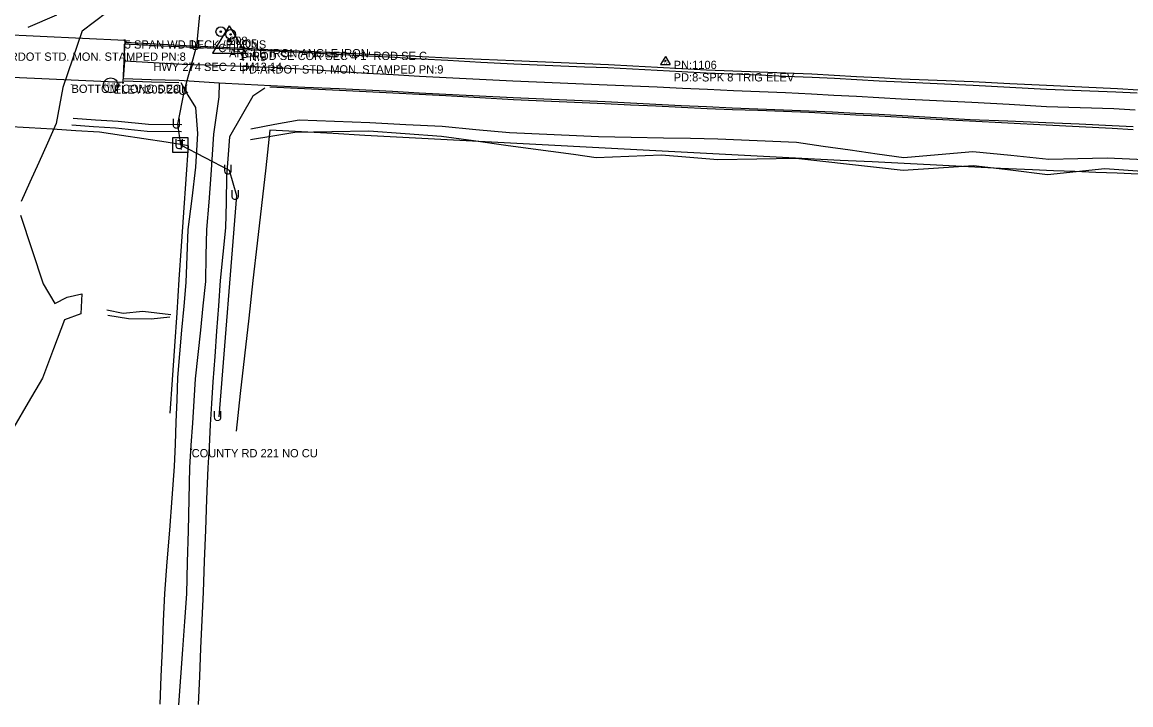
# Model space of a CAD drawing. Extents: x 1138803 to 1169983, y 1655906 to 1658226.
# Drawn here: x 1149238 to 1149908, y 1657086 to 1657498 of the extents above; entities that cross this region are included whole.
import ezdxf

# ---------------------------------------------------------------- set-up
doc = ezdxf.new("R2010")
doc.units = 0
for name, color, linetype in [('Default', 7, 'Continuous'), ('S_BRIDGE', 7, 'Continuous'), ('S_BRIDGE_ANNOT', 7, 'Continuous'), ('S_DITCHLINE', 7, 'Continuous'), ('S_EDGE_PAVEMENT', 7, 'Continuous'), ('S_GRAVEL_ROAD', 7, 'Continuous'), ('S_HIST_HIGH_WATER', 7, 'Continuous'), ('S_HIST_HIGH_WATER_ANNOT', 7, 'Continuous'), ('S_IRON_PIN', 7, 'Continuous'), ('S_IRON_PIN_ANNOT', 7, 'Continuous'), ('S_MSC_PT_SYM', 7, 'Continuous'), ('S_PAVEMENT_CROWN', 7, 'Continuous'), ('S_PRIMARY_CTL', 7, 'Continuous'), ('S_PRIMARY_CTL_ANNOT', 7, 'Continuous'), ('S_SECONDARY_CTL', 7, 'Continuous'), ('S_SECONDARY_CTL_ANNOT', 7, 'Continuous'), ('S_SHOULDER', 7, 'Continuous'), ('S_STR_PT_SYM', 7, 'Continuous'), ('S_STREAM', 7, 'Continuous'), ('S_SURVEY_TEXT_ANNOT', 7, 'Continuous'), ('S_TELEPHONE_UTILITIES', 7, 'Continuous'), ('S_TREE', 7, 'Continuous'), ('S_UNDERGROUND_CABLE', 7, 'Continuous'), ('S_UTL_PT_SYM', 7, 'Continuous')]:
    doc.layers.add(name, color=color, linetype=linetype)

msp = doc.modelspace()

# ---------------------------------------------------------------- linework, layer by layer
at = {"layer": 'S_BRIDGE'}
for p, q in [((1149223.22, 1657490.51), (1149300.02, 1657486.84)), ((1149300.02, 1657486.84), (1149298.91, 1657461.36)), ((1149298.91, 1657461.36), (1149221.93, 1657464.92))]:
    msp.add_line(p, q, dxfattribs=at)
at = {"layer": 'S_DITCHLINE'}
for points in [[(1149334.47, 1657435.85), (1149314.27, 1657436.03), (1149295.98, 1657437.74), (1149282.4, 1657438.69), (1149268.82, 1657439.65)], [(1149920.24, 1657414.54), (1149906.71, 1657415.09), (1149893.18, 1657415.65), (1149875.65, 1657415.27), (1149858.11, 1657414.9), (1149835.11, 1657417.24), (1149812.12, 1657419.57), (1149791.31, 1657417.7), (1149770.51, 1657415.83), (1149754.3, 1657418.14), (1149738.08, 1657420.44), (1149721.87, 1657422.74), (1149705.66, 1657425.05), (1149681.88, 1657426.12), (1149658.1, 1657427.19), (1149641.75, 1657427.48), (1149625.41, 1657427.78), (1149605.8, 1657428.18), (1149586.2, 1657428.59), (1149572.75, 1657429.17), (1149559.3, 1657429.76), (1149545.84, 1657430.34), (1149532.39, 1657430.92), (1149512.02, 1657432.82), (1149491.64, 1657434.71), (1149469.8, 1657435.85), (1149447.95, 1657437), (1149426.61, 1657437.82), (1149405.27, 1657438.65), (1149390.73, 1657435.92), (1149376.2, 1657433.2)], [(1149334.24, 1657431.56), (1149313.65, 1657431.84), (1149294.45, 1657433.82), (1149281.22, 1657434.67), (1149268, 1657435.52)], [(1149920.09, 1657407.18), (1149906, 1657408.18), (1149891.91, 1657409.19), (1149874.6, 1657407.43), (1149857.28, 1657405.67), (1149834.91, 1657408.41), (1149812.54, 1657411.15), (1149791.33, 1657409.71), (1149770.12, 1657408.28), (1149753.93, 1657410.09), (1149737.74, 1657411.91), (1149721.54, 1657413.72), (1149705.35, 1657415.54), (1149681.79, 1657415.15), (1149658.23, 1657414.75), (1149641.18, 1657416.15), (1149624.13, 1657417.54), (1149604.37, 1657416.75), (1149584.61, 1657415.96), (1149570.98, 1657417.8), (1149557.35, 1657419.64), (1149543.72, 1657421.48), (1149530.09, 1657423.32), (1149510.67, 1657426.05), (1149491.26, 1657428.79), (1149469.29, 1657430.41), (1149447.33, 1657432.03), (1149425.03, 1657431.56), (1149402.74, 1657431.1), (1149389.4, 1657428.88), (1149376.06, 1657426.67)], [(1149289.29, 1657324.09), (1149299.05, 1657322.02), (1149311, 1657323.36), (1149327.89, 1657321.3)], [(1149327.24, 1657319.71), (1149315.89, 1657318.44), (1149302.28, 1657318.68), (1149289.75, 1657320.58)]]:
    msp.add_lwpolyline(points, dxfattribs=at)
at = {"layer": 'S_EDGE_PAVEMENT'}
for points in [[(1149909.02, 1657434.65), (1149896.39, 1657435.26), (1149876.32, 1657436.16), (1149856.26, 1657437.06), (1149833.38, 1657437.96), (1149810.5, 1657438.86), (1149790, 1657440.06), (1149769.5, 1657441.26), (1149755.45, 1657441.96), (1149741.4, 1657442.66), (1149727.34, 1657443.36), (1149713.29, 1657444.06), (1149697.81, 1657444.69), (1149682.33, 1657445.32), (1149666.84, 1657445.95), (1149651.36, 1657446.58), (1149636.03, 1657447.36), (1149620.71, 1657448.13), (1149605.38, 1657448.9), (1149590.06, 1657449.68), (1149576.21, 1657450.3), (1149562.35, 1657450.92), (1149548.5, 1657451.54), (1149534.65, 1657452.17), (1149514.25, 1657453.18), (1149493.85, 1657454.2), (1149477.76, 1657455.02), (1149461.68, 1657455.84), (1149445.59, 1657456.66), (1149429.51, 1657457.48), (1149408.83, 1657458.42), (1149388.15, 1657459.35), (1149372.61, 1657460.19), (1149357.07, 1657461.03), (1149332.96, 1657462.66), (1149316.07, 1657463.07), (1149299.18, 1657463.49), (1149300.05, 1657474.26), (1149299.88, 1657484.48)], [(1149911.44, 1657454.9), (1149898.49, 1657455.58), (1149877.6, 1657456.34), (1149856.72, 1657457.11), (1149834.5, 1657458.33), (1149812.29, 1657459.56), (1149790.71, 1657460.55), (1149769.13, 1657461.55), (1149755.61, 1657462.27), (1149742.1, 1657462.98), (1149728.58, 1657463.69), (1149715.06, 1657464.4), (1149699.1, 1657465.06), (1149683.13, 1657465.72), (1149667.16, 1657466.38), (1149651.19, 1657467.03), (1149636.34, 1657467.81), (1149621.49, 1657468.59), (1149606.64, 1657469.36), (1149591.79, 1657470.14), (1149577.57, 1657470.71), (1149563.36, 1657471.28), (1149549.14, 1657471.86), (1149534.92, 1657472.43), (1149515.05, 1657473.51), (1149495.18, 1657474.59), (1149479.18, 1657475.49), (1149463.18, 1657476.38), (1149447.18, 1657477.28), (1149431.18, 1657478.17), (1149410.39, 1657479.22), (1149389.59, 1657480.27), (1149376.52, 1657480.89), (1149363.44, 1657481.5), (1149350.37, 1657482.12), (1149337.29, 1657482.74), (1149318.58, 1657483.61), (1149299.88, 1657484.48)]]:
    msp.add_lwpolyline(points, dxfattribs=at)
at = {"layer": 'S_GRAVEL_ROAD'}
for points in [[(1149333.8, 1657461.4), (1149338.18, 1657453.72), (1149342.77, 1657446.24), (1149344.05, 1657430.53), (1149342.78, 1657410.16), (1149340.46, 1657391.36), (1149338.13, 1657372.56), (1149337.49, 1657356.59), (1149336.84, 1657340.62), (1149335.61, 1657326.26), (1149334.37, 1657311.89), (1149333.14, 1657297.53), (1149331.91, 1657283.17), (1149331.41, 1657269.75), (1149330.91, 1657256.32), (1149330.41, 1657242.9), (1149329.91, 1657229.48), (1149328.44, 1657210.29), (1149326.96, 1657191.1), (1149325.49, 1657171.9), (1149324.02, 1657152.71), (1149323.3, 1657136.05), (1149322.57, 1657119.38), (1149321.85, 1657102.71), (1149321.12, 1657086.05)], [(1149384.53, 1657458.05), (1149377.43, 1657453.11), (1149370.36, 1657440.87), (1149363.28, 1657428.63), (1149361.44, 1657404.59), (1149361.19, 1657389.08), (1149360.93, 1657373.57), (1149359.34, 1657357.69), (1149357.74, 1657341.81), (1149356.62, 1657326.5), (1149355.5, 1657311.19), (1149354.37, 1657295.88), (1149353.25, 1657280.58), (1149352.47, 1657267.58), (1149351.69, 1657254.59), (1149350.91, 1657241.59), (1149350.13, 1657228.6), (1149349.43, 1657209.85), (1149348.73, 1657191.11), (1149348.03, 1657172.36), (1149347.33, 1657153.62), (1149346.58, 1657136.67), (1149345.82, 1657119.72), (1149345.07, 1657102.77), (1149344.31, 1657085.81)]]:
    msp.add_lwpolyline(points, dxfattribs=at)
at = {"layer": 'S_HIST_HIGH_WATER'}
msp.add_circle((1149291.58, 1657459.68), 4.5, dxfattribs=at)
at = {"layer": 'S_IRON_PIN'}
for centre, radius in [((1149358.03, 1657492.07), 2.91), ((1149358.03, 1657492.07), 0.411), ((1149358.03, 1657492.07), 0.262), ((1149358.03, 1657492.07), 0.212), ((1149358.03, 1657492.07), 0.145), ((1149358.03, 1657492.07), 0.0822), ((1149358.03, 1657492.07), 0.0581), ((1149363.94, 1657490.43), 2.91), ((1149363.94, 1657490.43), 0.411), ((1149363.94, 1657490.43), 0.262), ((1149363.94, 1657490.43), 0.212), ((1149363.94, 1657490.43), 0.145), ((1149363.94, 1657490.43), 0.0822), ((1149363.94, 1657490.43), 0.0581)]:
    msp.add_circle(centre, radius, dxfattribs=at)
at = {"layer": 'S_MSC_PT_SYM'}
for points in [[(1149317.4, 1657473.33), (1149317.4, 1657473.38), (1149317.4, 1657473.33), (1149317.35, 1657473.33), (1149317.4, 1657473.33), (1149317.4, 1657473.28), (1149317.4, 1657473.33), (1149317.45, 1657473.33)], [(1149369.55, 1657472.44), (1149369.55, 1657472.49), (1149369.55, 1657472.44), (1149369.5, 1657472.44), (1149369.55, 1657472.44), (1149369.55, 1657472.39), (1149369.55, 1657472.44), (1149369.6, 1657472.44)], [(1149376.53, 1657471.67), (1149376.53, 1657471.72), (1149376.53, 1657471.67), (1149376.48, 1657471.67), (1149376.53, 1657471.67), (1149376.53, 1657471.62), (1149376.53, 1657471.67), (1149376.58, 1657471.67)], [(1149267.88, 1657460.1), (1149267.88, 1657460.15), (1149267.88, 1657460.1), (1149267.83, 1657460.1), (1149267.88, 1657460.1), (1149267.88, 1657460.05), (1149267.88, 1657460.1), (1149267.93, 1657460.1)], [(1149340.42, 1657240.03), (1149340.42, 1657240.08), (1149340.42, 1657240.03), (1149340.37, 1657240.03), (1149340.42, 1657240.03), (1149340.42, 1657239.98), (1149340.42, 1657240.03), (1149340.47, 1657240.03)]]:
    msp.add_lwpolyline(points, dxfattribs=at)
at = {"layer": 'S_PAVEMENT_CROWN'}
for points in [[(1149910.19, 1657444.66), (1149897.36, 1657445.39), (1149877, 1657446.08), (1149856.63, 1657446.77), (1149834.07, 1657448.08), (1149811.51, 1657449.39), (1149790.2, 1657450.39), (1149768.89, 1657451.39), (1149755.35, 1657452.14), (1149741.81, 1657452.88), (1149728.27, 1657453.62), (1149714.72, 1657454.36), (1149699.02, 1657455.05), (1149683.31, 1657455.74), (1149667.61, 1657456.42), (1149651.91, 1657457.11), (1149636.76, 1657457.79), (1149621.62, 1657458.46), (1149606.47, 1657459.14), (1149591.33, 1657459.81), (1149577.1, 1657460.43), (1149562.88, 1657461.04), (1149548.66, 1657461.65), (1149534.44, 1657462.27), (1149514.25, 1657463.19), (1149494.06, 1657464.12), (1149478.11, 1657465.05), (1149462.17, 1657465.97), (1149446.22, 1657466.9), (1149430.28, 1657467.82), (1149409.4, 1657469.15), (1149388.53, 1657470.48), (1149375.07, 1657470.92), (1149361.6, 1657471.35), (1149348.14, 1657471.78), (1149334.68, 1657472.22), (1149317.33, 1657473.24), (1149299.99, 1657474.25)], [(1149357.07, 1657461.03), (1149356.75, 1657452.7), (1149353.58, 1657430.25), (1149352.1, 1657405.71), (1149350.77, 1657389.18), (1149349.45, 1657372.64), (1149349.09, 1657356.92), (1149348.74, 1657341.19), (1149347.2, 1657326.51), (1149345.67, 1657311.82), (1149344.14, 1657297.13), (1149342.6, 1657282.45), (1149341.74, 1657269.06), (1149340.88, 1657255.68), (1149340.02, 1657242.29), (1149339.15, 1657228.91), (1149338.69, 1657209.82), (1149338.23, 1657190.72), (1149337.77, 1657171.63), (1149337.31, 1657152.53), (1149336.1, 1657135.79), (1149334.89, 1657119.05), (1149333.68, 1657102.31), (1149332.46, 1657085.57)]]:
    msp.add_lwpolyline(points, dxfattribs=at)
at = {"layer": 'S_PRIMARY_CTL'}
for p, q in [((1149363.12, 1657495.5), (1149353.09, 1657478.99)), ((1149363.12, 1657495.5), (1149372.95, 1657478.99)), ((1149353.09, 1657478.99), (1149372.95, 1657478.99))]:
    msp.add_line(p, q, dxfattribs=at)
for radius in [1.04, 0.609, 0.344]:
    msp.add_circle((1149363.12, 1657486.8), radius, dxfattribs=at)
at = {"layer": 'S_SECONDARY_CTL'}
for p, q in [((1149626.5, 1657477.12), (1149623.49, 1657472.16)), ((1149626.5, 1657477.12), (1149629.45, 1657472.16)), ((1149623.49, 1657472.16), (1149629.45, 1657472.16))]:
    msp.add_line(p, q, dxfattribs=at)
for radius in [0.311, 0.183, 0.103]:
    msp.add_circle((1149626.5, 1657474.51), radius, dxfattribs=at)
at = {"layer": 'S_SHOULDER'}
for points in [[(1149912.29, 1657456.81), (1149899.47, 1657457.49), (1149878.07, 1657458.56), (1149856.68, 1657459.63), (1149834.5, 1657460.67), (1149812.31, 1657461.71), (1149790.62, 1657462.56), (1149768.93, 1657463.41), (1149755.45, 1657464.15), (1149741.97, 1657464.88), (1149728.49, 1657465.61), (1149715.01, 1657466.35), (1149699.08, 1657466.98), (1149683.15, 1657467.61), (1149667.22, 1657468.25), (1149651.29, 1657468.88), (1149636.5, 1657469.68), (1149621.72, 1657470.47), (1149606.94, 1657471.27), (1149592.16, 1657472.07), (1149577.85, 1657472.68), (1149563.54, 1657473.3), (1149549.22, 1657473.92), (1149534.91, 1657474.54), (1149515.25, 1657475.31), (1149495.59, 1657476.09), (1149479.54, 1657476.85), (1149463.49, 1657477.61), (1149447.44, 1657478.36), (1149431.39, 1657479.12), (1149410.57, 1657480.03), (1149389.75, 1657480.95), (1149376.59, 1657481.61), (1149363.42, 1657482.27), (1149350.26, 1657482.93), (1149337.1, 1657483.59), (1149318.66, 1657484.61), (1149300.21, 1657485.62)], [(1149332.67, 1657461.12), (1149316.18, 1657461.67), (1149299.7, 1657462.22)], [(1149909.07, 1657432.84), (1149896.37, 1657433.56), (1149876.39, 1657434.58), (1149856.41, 1657435.61), (1149833.32, 1657436.78), (1149810.23, 1657437.94), (1149789.94, 1657439.09), (1149769.65, 1657440.24), (1149755.54, 1657440.98), (1149741.43, 1657441.72), (1149727.32, 1657442.46), (1149713.21, 1657443.2), (1149697.82, 1657443.79), (1149682.42, 1657444.37), (1149667.02, 1657444.96), (1149651.63, 1657445.54), (1149636.21, 1657446.29), (1149620.8, 1657447.03), (1149605.38, 1657447.78), (1149589.97, 1657448.52), (1149576.16, 1657449.13), (1149562.35, 1657449.73), (1149548.54, 1657450.33), (1149534.74, 1657450.93), (1149514.35, 1657452.16), (1149493.97, 1657453.39), (1149477.9, 1657454.2), (1149461.83, 1657455), (1149445.75, 1657455.81), (1149429.68, 1657456.61), (1149408.64, 1657457.59), (1149387.59, 1657458.57)]]:
    msp.add_lwpolyline(points, dxfattribs=at)
at = {"layer": 'S_STR_PT_SYM'}
for points in [[(1149300.02, 1657486.84), (1149300.02, 1657487.34), (1149300.02, 1657486.84), (1149299.52, 1657486.84), (1149300.02, 1657486.84), (1149300.02, 1657486.34), (1149300.02, 1657486.84), (1149300.52, 1657486.84)], [(1149298.91, 1657461.36), (1149298.91, 1657461.86), (1149298.91, 1657461.36), (1149298.41, 1657461.36), (1149298.91, 1657461.36), (1149298.91, 1657460.86), (1149298.91, 1657461.36), (1149299.41, 1657461.36)]]:
    msp.add_lwpolyline(points, dxfattribs=at)
at = {"layer": 'S_STREAM'}
for points in [[(1149274.34, 1657492.65), (1149289.26, 1657503.87)], [(1149241.68, 1657494.79), (1149258.94, 1657502.25)], [(1149274.34, 1657492.65), (1149268.47, 1657475.51), (1149262.59, 1657458.38)], [(1149262.59, 1657458.38), (1149258.7, 1657436.56), (1149253.37, 1657424.79), (1149248.05, 1657413.02), (1149242.72, 1657401.25), (1149237.39, 1657389.48)], [(1149236.99, 1657381.35), (1149243.85, 1657360.58), (1149250.71, 1657339.82), (1149257.71, 1657327.85), (1149265.2, 1657331.81), (1149274.19, 1657333.76), (1149273.54, 1657321.61), (1149263.63, 1657318.06), (1149256.96, 1657300.5), (1149250.28, 1657282.93), (1149241.66, 1657268.04), (1149233.04, 1657253.15)]]:
    msp.add_lwpolyline(points, dxfattribs=at)
at = {"layer": 'S_TELEPHONE_UTILITIES'}
msp.add_lwpolyline([(1149329.08, 1657419.12), (1149329.08, 1657428.12), (1149338.08, 1657428.12), (1149338.08, 1657419.12)], close=True, dxfattribs=at)
at = {"layer": 'S_TREE'}
for points in [[(1149327.49, 1657261.68), (1149328.86, 1657281.87), (1149330.23, 1657302.06), (1149331.59, 1657322.25), (1149332.96, 1657342.43), (1149334.33, 1657362.62), (1149335.7, 1657382.81), (1149337.06, 1657403), (1149338.43, 1657423.19), (1149325.01, 1657425.25), (1149311.58, 1657427.32), (1149298.15, 1657429.38), (1149284.73, 1657431.45), (1149270.56, 1657432.28), (1149256.39, 1657433.11), (1149242.21, 1657433.94), (1149228.04, 1657434.77)], [(1149911.97, 1657406.04), (1149899.21, 1657406.54), (1149886.44, 1657407.04), (1149873.68, 1657407.55), (1149860.92, 1657408.05), (1149848.16, 1657408.55), (1149828.81, 1657409.52), (1149809.46, 1657410.49), (1149790.12, 1657411.46), (1149770.77, 1657412.43), (1149751.42, 1657413.4), (1149732.08, 1657414.37), (1149712.73, 1657415.34), (1149693.38, 1657416.3), (1149674.28, 1657417.32), (1149655.17, 1657418.33), (1149636.07, 1657419.34), (1149616.96, 1657420.35), (1149597.86, 1657421.37), (1149578.75, 1657422.38), (1149559.65, 1657423.39), (1149540.54, 1657424.4), (1149521.44, 1657425.42), (1149502.33, 1657426.43), (1149483.23, 1657427.44), (1149464.12, 1657428.45), (1149445.02, 1657429.47), (1149425.91, 1657430.48), (1149406.81, 1657431.49), (1149387.7, 1657432.5), (1149385.14, 1657409.8), (1149382.58, 1657387.11), (1149380.03, 1657364.41), (1149377.47, 1657341.71), (1149374.91, 1657319.01), (1149372.35, 1657296.31), (1149369.79, 1657273.61), (1149367.23, 1657250.91)]]:
    msp.add_lwpolyline(points, dxfattribs=at)
at = {"layer": 'S_UNDERGROUND_CABLE'}
for p, q in [((1149345.79, 1657508.45), (1149343.42, 1657483.52)), ((1149343.42, 1657483.52), (1149335.82, 1657456.45)), ((1149335.82, 1657456.45), (1149331.94, 1657436.13)), ((1149331.94, 1657436.13), (1149333.63, 1657423.71)), ((1149333.63, 1657423.71), (1149363.04, 1657408.4)), ((1149363.04, 1657408.4), (1149367.44, 1657393.06)), ((1149367.44, 1657393.06), (1149356.83, 1657259.54))]:
    msp.add_line(p, q, dxfattribs=at)
at = {"layer": 'S_UTL_PT_SYM'}
for points in [[(1149369.55, 1657472.44), (1149369.55, 1657472.49), (1149369.55, 1657472.44), (1149369.5, 1657472.44), (1149369.55, 1657472.44), (1149369.55, 1657472.39), (1149369.55, 1657472.44), (1149369.6, 1657472.44)], [(1149376.53, 1657471.67), (1149376.53, 1657471.72), (1149376.53, 1657471.67), (1149376.48, 1657471.67), (1149376.53, 1657471.67), (1149376.53, 1657471.62), (1149376.53, 1657471.67), (1149376.58, 1657471.67)]]:
    msp.add_lwpolyline(points, dxfattribs=at)

# ---------------------------------------------------------------- texts
at = {"layer": 'Default'}
for p in [(1149339.79, 1657480.98), (1149332.19, 1657453.91), (1149328.31, 1657433.59), (1149330, 1657421.17), (1149359.42, 1657405.85), (1149363.81, 1657390.52), (1149353.2, 1657256.99)]:
    msp.add_text('U', height=6, rotation=360, dxfattribs=at).set_placement(p)
at = {"layer": 'S_BRIDGE_ANNOT'}
msp.add_text('5 SPAN WD DECK /PILONS', height=5, dxfattribs=at).set_placement((1149300.02, 1657481.84))
at = {"layer": 'S_HIST_HIGH_WATER'}
msp.add_text('HHW', height=3, rotation=360, dxfattribs=at).set_placement((1149287.49, 1657458.18))
at = {"layer": 'S_HIST_HIGH_WATER_ANNOT'}
msp.add_text(' ELEV:205.28', height=5, dxfattribs=at).set_placement((1149291.58, 1657454.68))
at = {"layer": 'S_IRON_PIN_ANNOT'}
for s, p in [('208', (1149363.03, 1657484.07)), ('205', (1149368.94, 1657482.43)), ('ANGLE IRON ANGLE IRON', (1149363.03, 1657476.57)), ('1" ROD SE COR SEC 4 1" ROD SE C', (1149368.94, 1657474.93))]:
    msp.add_text(s, height=5, dxfattribs=at).set_placement(p)
at = {"layer": 'S_PRIMARY_CTL'}
msp.add_text('CTL', height=5, rotation=360, dxfattribs=at).set_placement((1149356.54, 1657479.72))
at = {"layer": 'S_PRIMARY_CTL_ANNOT'}
for s, p in [('PD:ARDOT STD. MON. STAMPED PN:8', (1149215.03, 1657474.48)), ('PN:9', (1149370.62, 1657474.3)), ('PD:ARDOT STD. MON. STAMPED PN:9', (1149370.62, 1657466.8))]:
    msp.add_text(s, height=5, dxfattribs=at).set_placement(p)
at = {"layer": 'S_SECONDARY_CTL'}
msp.add_text('TV', height=1.5, rotation=360, dxfattribs=at).set_placement((1149625.29, 1657472.49))
at = {"layer": 'S_SECONDARY_CTL_ANNOT'}
for s, p in [('PN:1106', (1149631.5, 1657469.51)), ('PD:8-SPK 8 TRIG ELEV', (1149631.5, 1657462.01))]:
    msp.add_text(s, height=5, dxfattribs=at).set_placement(p)
at = {"layer": 'S_SURVEY_TEXT_ANNOT'}
for s, p in [('HWY 274 SEC 2 LM13.14', (1149317.4, 1657468.33)), ('BOTTOM CONC DECK', (1149267.88, 1657455.1)), ('COUNTY RD 221 NO CU', (1149340.42, 1657235.03))]:
    msp.add_text(s, height=5, dxfattribs=at).set_placement(p)
at = {"layer": 'S_TELEPHONE_UTILITIES'}
msp.add_text('T', height=6, rotation=360, dxfattribs=at).set_placement((1149331.64, 1657420.62))

doc.saveas('drawing.dxf')
